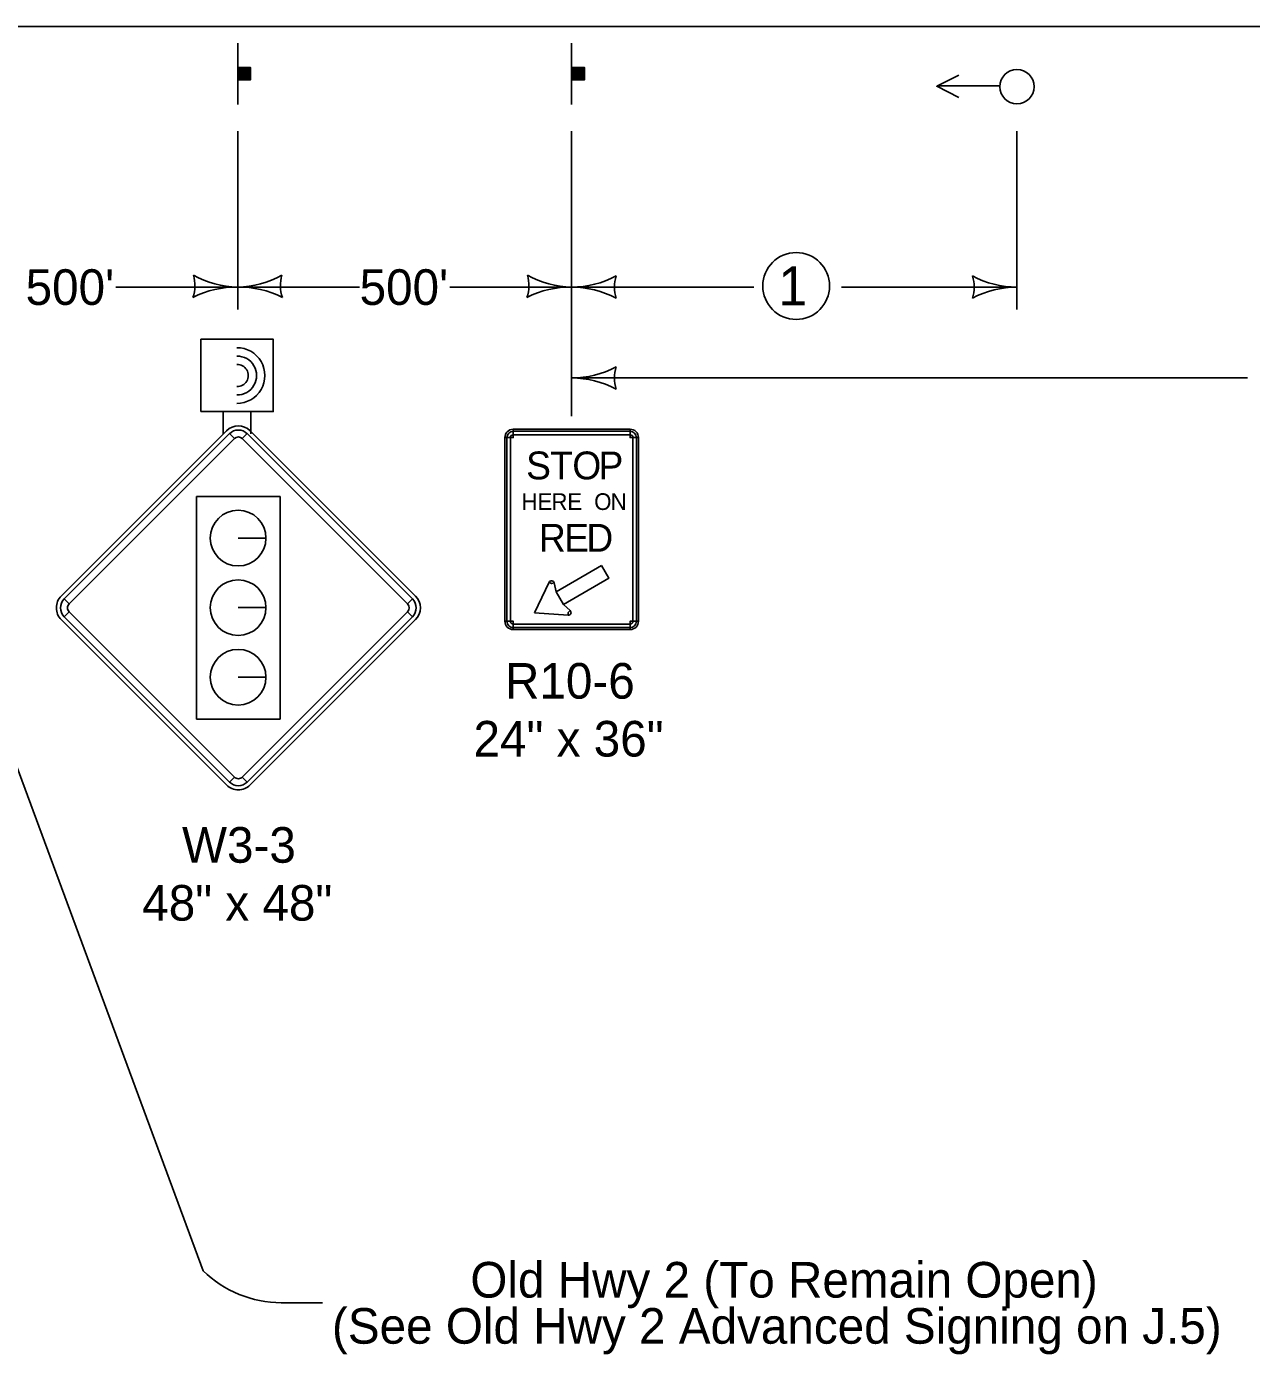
# Model space of a CAD drawing. Extents: x -2134934 to -2119606, y -2139046 to -2137036.
# Drawn here: x -2134479 to -2133929, y -2138264 to -2137668 of the extents above; entities that cross this region are included whole.
import ezdxf

# ---------------------------------------------------------------- set-up
doc = ezdxf.new("R2010")
doc.units = 0
for name, color, linetype in [('dsnCellElements', 7, 'Continuous'), ('dsnStdLabel', 7, 'Continuous'), ('dsnStdLineWork', 7, 'Continuous'), ('Level 2', 7, 'Continuous')]:
    doc.layers.add(name, color=color, linetype=linetype)

msp = doc.modelspace()

# ---------------------------------------------------------------- linework, layer by layer
at = {"layer": 'dsnCellElements'}
for centre, radius, start, end in [((-2134234.44, -2137783.48), 42.5, 270, 298.07249), ((-2134198.81, -2137825.98), 16.42, 162.26665, 197.73335), ((-2134234.44, -2137868.48), 42.5, 61.92751, 90)]:
    msp.add_arc(centre, radius, start, end, dxfattribs=at)
at = {"layer": 'dsnStdLabel'}
for p, q in [((-2134389.44, -2137849.65), (-2134463.68, -2137923.9)), ((-2134388.11, -2137850.98), (-2134385.9, -2137853.19)), ((-2134382.37, -2137853.19), (-2134380.16, -2137850.98)), ((-2134304.59, -2137923.9), (-2134378.83, -2137849.65)), ((-2134264.44, -2137852.75), (-2134260.69, -2137852.75)), ((-2134263.5, -2137852.75), (-2134261.94, -2137852.75)), ((-2134260.69, -2137852.75), (-2134260.69, -2137849)), ((-2134260.69, -2137851.5), (-2134260.69, -2137849.93)), ((-2134208.19, -2137849), (-2134208.19, -2137852.75)), ((-2134208.19, -2137849.93), (-2134208.19, -2137851.5)), ((-2134208.19, -2137852.75), (-2134204.44, -2137852.75)), ((-2134206.94, -2137852.75), (-2134205.38, -2137852.75)), ((-2134371.73, -2137897.87), (-2134384.23, -2137897.87)), ((-2134384.23, -2137897.87), (-2134371.73, -2137897.87)), ((-2134244.58, -2137917.73), (-2134243.48, -2137918.31)), ((-2134243.48, -2137918.31), (-2134242.26, -2137918.04)), ((-2134460.15, -2137927.43), (-2134462.36, -2137925.22)), ((-2134371.73, -2137929.12), (-2134384.23, -2137929.12)), ((-2134384.23, -2137929.12), (-2134371.73, -2137929.12)), ((-2134305.91, -2137925.22), (-2134308.12, -2137927.43)), ((-2134235.13, -2137930.38), (-2134235.98, -2137931.3)), ((-2134463.68, -2137934.5), (-2134389.44, -2138008.75)), ((-2134462.36, -2137933.18), (-2134460.15, -2137930.97)), ((-2134378.83, -2138008.75), (-2134304.59, -2137934.5)), ((-2134308.12, -2137930.97), (-2134305.91, -2137933.18)), ((-2134260.69, -2137935.24), (-2134264.44, -2137935.24)), ((-2134261.94, -2137935.24), (-2134263.5, -2137935.24)), ((-2134260.69, -2137938.99), (-2134260.69, -2137935.24)), ((-2134260.69, -2137938.06), (-2134260.69, -2137936.49)), ((-2134235.98, -2137931.3), (-2134236.03, -2137932.55)), ((-2134204.44, -2137935.24), (-2134208.19, -2137935.24)), ((-2134208.19, -2137935.24), (-2134208.19, -2137938.99)), ((-2134208.19, -2137936.49), (-2134208.19, -2137938.06)), ((-2134205.38, -2137935.24), (-2134206.94, -2137935.24)), ((-2134371.73, -2137960.37), (-2134384.23, -2137960.37)), ((-2134384.23, -2137960.37), (-2134371.73, -2137960.37)), ((-2134385.9, -2138005.21), (-2134388.11, -2138007.42)), ((-2134380.16, -2138007.42), (-2134382.37, -2138005.21))]:
    msp.add_line(p, q, dxfattribs=at)
for points in [[(-2134388.11, -2137850.98), (-2134462.36, -2137925.22), (-2134460.15, -2137927.43), (-2134385.9, -2137853.19), (-2134388.11, -2137850.98)], [(-2134305.91, -2137925.22), (-2134380.16, -2137850.98), (-2134382.37, -2137853.19), (-2134308.12, -2137927.43), (-2134305.91, -2137925.22)], [(-2134260.69, -2137938.99), (-2134208.19, -2137938.99), (-2134208.19, -2137935.24), (-2134204.44, -2137935.24), (-2134204.44, -2137852.75), (-2134208.19, -2137852.75), (-2134208.19, -2137849), (-2134260.69, -2137849), (-2134260.69, -2137852.75), (-2134264.44, -2137852.75), (-2134264.44, -2137935.24), (-2134260.69, -2137935.24), (-2134260.69, -2137938.99)], [(-2134261.94, -2137852.75), (-2134261.94, -2137935.24), (-2134263.5, -2137935.24), (-2134263.5, -2137852.75), (-2134261.94, -2137852.75)], [(-2134208.19, -2137851.5), (-2134260.69, -2137851.5), (-2134260.69, -2137849.93), (-2134208.19, -2137849.93), (-2134208.19, -2137851.5)], [(-2134206.94, -2137935.24), (-2134206.94, -2137852.75), (-2134205.38, -2137852.75), (-2134205.38, -2137935.24), (-2134206.94, -2137935.24)], [(-2134365.4, -2137879.26), (-2134402.87, -2137879.26), (-2134402.87, -2137979.15), (-2134365.4, -2137979.15), (-2134365.4, -2137879.26)], [(-2134221.07, -2137910.24), (-2134217.79, -2137915.93), (-2134238.1, -2137927.65), (-2134241.38, -2137921.97), (-2134221.07, -2137910.24)], [(-2134251.09, -2137931.37), (-2134236.03, -2137932.55), (-2134235.98, -2137931.3), (-2134235.13, -2137930.38), (-2134238.1, -2137927.65), (-2134241.38, -2137921.97), (-2134242.26, -2137918.04), (-2134243.48, -2137918.31), (-2134244.58, -2137917.73), (-2134251.09, -2137931.37)], [(-2134462.36, -2137933.18), (-2134388.11, -2138007.42), (-2134385.9, -2138005.21), (-2134460.15, -2137930.97), (-2134462.36, -2137933.18)], [(-2134380.16, -2138007.42), (-2134305.91, -2137933.18), (-2134308.12, -2137930.97), (-2134382.37, -2138005.21), (-2134380.16, -2138007.42)], [(-2134260.69, -2137936.49), (-2134208.19, -2137936.49), (-2134208.19, -2137938.06), (-2134260.69, -2137938.06), (-2134260.69, -2137936.49)]]:
    msp.add_lwpolyline(points, close=True, dxfattribs=at)
for centre in [(-2134384.23, -2137897.87), (-2134384.23, -2137929.12), (-2134384.23, -2137960.37)]:
    msp.add_circle(centre, 12.5, dxfattribs=at)
for centre, radius, start, end in [((-2134384.14, -2137854.96), 7.5, 44.99999, 134.99974), ((-2134384.14, -2137854.96), 5.62, 44.99999, 134.99974), ((-2134384.14, -2137854.96), 2.5, 44.99999, 134.99974), ((-2134260.69, -2137852.75), 3.75, 90.00021, 179.99985), ((-2134260.69, -2137852.75), 2.81, 90.00021, 179.99985), ((-2134260.69, -2137852.75), 1.25, 90.00021, 179.99985), ((-2134208.19, -2137852.75), 3.75, 0, 90.00021), ((-2134208.19, -2137852.75), 2.81, 0, 90.00021), ((-2134208.19, -2137852.75), 1.25, 0, 90.00021), ((-2134243.48, -2137918.31), 1.25, 12.62232, 152.27557), ((-2134458.38, -2137929.2), 7.5, 134.99974, 224.99995), ((-2134309.89, -2137929.2), 7.5, 315.00016, 44.9998), ((-2134458.38, -2137929.2), 5.62, 134.99974, 224.99995), ((-2134458.38, -2137929.2), 2.5, 134.99974, 224.99995), ((-2134309.89, -2137929.2), 2.5, 315.00016, 44.9998), ((-2134309.89, -2137929.2), 5.62, 315.00016, 44.9998), ((-2134235.98, -2137931.3), 1.25, 267.72427, 47.37758), ((-2134260.69, -2137935.24), 3.75, 179.99985, 270.00006), ((-2134260.69, -2137935.24), 2.81, 179.99985, 270.00006), ((-2134260.69, -2137935.24), 1.25, 179.99985, 270.00006), ((-2134208.19, -2137935.24), 3.75, 270.00006, 0.00027), ((-2134208.19, -2137935.24), 2.81, 270.00006, 0.00027), ((-2134208.19, -2137935.24), 1.25, 270.00006, 0.00027), ((-2134384.14, -2138003.45), 5.62, 224.99995, 315.00016), ((-2134384.14, -2138003.45), 2.5, 224.99995, 315.00016), ((-2134384.14, -2138003.45), 7.5, 224.99995, 315.00016)]:
    msp.add_arc(centre, radius, start, end, dxfattribs=at)
at = {"layer": 'dsnStdLineWork'}
msp.add_line((-2134884.44, -2137668.16), (-2133384.44, -2137668.16), dxfattribs=at)
msp.add_line((-2134884.44, -2137668.16), (-2133384.44, -2137668.16), dxfattribs=at)
at = {"layer": 'Level 2'}
for p, q in [((-2134384.44, -2137675.66), (-2134384.44, -2137703.16)), ((-2134234.44, -2137675.66), (-2134234.44, -2137703.16)), ((-2134384.03, -2137692.11), (-2134384.03, -2137686.52)), ((-2134383.75, -2137686.52), (-2134383.75, -2137692.11)), ((-2134383.48, -2137692.11), (-2134383.48, -2137686.52)), ((-2134383.22, -2137686.52), (-2134383.22, -2137692.11)), ((-2134383, -2137692.11), (-2134383, -2137686.52)), ((-2134382.79, -2137686.52), (-2134382.79, -2137692.11)), ((-2134382.45, -2137692.11), (-2134382.45, -2137686.52)), ((-2134382.19, -2137686.52), (-2134382.19, -2137692.11)), ((-2134381.97, -2137692.11), (-2134381.98, -2137686.52)), ((-2134381.65, -2137686.52), (-2134381.65, -2137692.11)), ((-2134381.27, -2137692.11), (-2134381.27, -2137686.52)), ((-2134380.84, -2137686.52), (-2134380.84, -2137692.11)), ((-2134380.62, -2137692.11), (-2134380.63, -2137686.52)), ((-2134380.2, -2137686.52), (-2134380.18, -2137692.11)), ((-2134379.98, -2137692.11), (-2134379.98, -2137686.52)), ((-2134379.66, -2137686.52), (-2134379.66, -2137692.11)), ((-2134379.43, -2137692.11), (-2134379.43, -2137686.52)), ((-2134379.12, -2137686.52), (-2134379.12, -2137692.11)), ((-2134234.03, -2137692.11), (-2134234.03, -2137686.52)), ((-2134233.75, -2137686.52), (-2134233.75, -2137692.11)), ((-2134233.49, -2137692.11), (-2134233.49, -2137686.52)), ((-2134233.22, -2137686.52), (-2134233.22, -2137692.11)), ((-2134233, -2137692.11), (-2134233, -2137686.52)), ((-2134232.79, -2137686.52), (-2134232.79, -2137692.11)), ((-2134232.45, -2137692.11), (-2134232.45, -2137686.52)), ((-2134232.19, -2137686.52), (-2134232.19, -2137692.11)), ((-2134231.97, -2137692.11), (-2134231.99, -2137686.52)), ((-2134231.65, -2137686.52), (-2134231.65, -2137692.11)), ((-2134231.27, -2137692.11), (-2134231.27, -2137686.52)), ((-2134230.84, -2137686.52), (-2134230.84, -2137692.11)), ((-2134230.62, -2137692.11), (-2134230.64, -2137686.52)), ((-2134230.2, -2137686.52), (-2134230.19, -2137692.11)), ((-2134229.98, -2137692.11), (-2134229.98, -2137686.52)), ((-2134229.66, -2137686.52), (-2134229.66, -2137692.11)), ((-2134229.44, -2137692.11), (-2134229.44, -2137686.52)), ((-2134229.12, -2137686.52), (-2134229.12, -2137692.11)), ((-2134042.18, -2137694.79), (-2134070.12, -2137694.79)), ((-2134399.95, -2138226.87), (-2134593.95, -2137702.64)), ((-2134384.44, -2137795.16), (-2134384.44, -2137715.16)), ((-2134234.44, -2137843.11), (-2134234.44, -2137715.16)), ((-2134034.44, -2137795.16), (-2134034.44, -2137715.16)), ((-2134439.19, -2137785.16), (-2134384.44, -2137785.16)), ((-2134384.44, -2137785.16), (-2134329.69, -2137785.16)), ((-2134289.19, -2137785.16), (-2134234.44, -2137785.16)), ((-2134234.44, -2137785.16), (-2134152.68, -2137785.16)), ((-2134113.22, -2137785.16), (-2134034.44, -2137785.16)), ((-2134234.44, -2137825.98), (-2133930.88, -2137825.98)), ((-2134390.98, -2137841.1), (-2134390.98, -2137851.1)), ((-2134378.48, -2137841.1), (-2134378.48, -2137851.1)), ((-2134364.86, -2138241.25), (-2134346.4, -2138241.25))]:
    msp.add_line(p, q, dxfattribs=at)
for points in [[(-2134384.35, -2137692.11), (-2134384.35, -2137686.48), (-2134378.72, -2137686.48), (-2134378.72, -2137692.11)], [(-2134234.35, -2137692.11), (-2134234.35, -2137686.48), (-2134228.72, -2137686.48), (-2134228.72, -2137692.11)], [(-2134400.98, -2137841.1), (-2134400.98, -2137808.6), (-2134368.48, -2137808.6), (-2134368.48, -2137841.1)]]:
    msp.add_lwpolyline(points, close=True, dxfattribs=at)
msp.add_lwpolyline([(-2134060.49, -2137689.98), (-2134070.49, -2137694.98), (-2134060.49, -2137699.98)], dxfattribs=at)
for centre, radius in [((-2134034.44, -2137695.16), 7.74), ((-2134133.59, -2137784.66), 15)]:
    msp.add_circle(centre, radius, dxfattribs=at)
for centre, radius, start, end in [((-2134420.06, -2137784.54), 16.42, 341.26665, 16.73335), ((-2134383.69, -2137742.67), 42.5, 240.92751, 268.9824), ((-2134385.2, -2137742.67), 42.5, 271.0176, 299.07249), ((-2134348.82, -2137784.54), 16.42, 163.26665, 198.73335), ((-2134270.06, -2137784.54), 16.42, 341.26665, 16.73335), ((-2134233.69, -2137742.67), 42.5, 240.92751, 268.9824), ((-2134234.44, -2137742.66), 42.5, 270, 298.07249), ((-2134198.81, -2137785.16), 16.42, 162.26665, 197.73335), ((-2134070.08, -2137785.16), 16.42, 342.26665, 17.73335), ((-2134034.44, -2137742.66), 42.5, 241.92751, 270), ((-2134385.17, -2137827.65), 42.5, 89.0176, 117.07249), ((-2134383.71, -2137827.65), 42.5, 62.92751, 90.9824), ((-2134235.17, -2137827.65), 42.5, 89.0176, 117.07249), ((-2134234.44, -2137827.66), 42.5, 61.92751, 90), ((-2134034.44, -2137827.66), 42.5, 90, 118.07249), ((-2134384.72, -2137824.87), 12.5, 269.40414, 90.54446), ((-2134384.72, -2137824.87), 12.5, 269.40414, 90.54446), ((-2134384.72, -2137824.87), 8.75, 269.40414, 90.54446), ((-2134384.72, -2137824.87), 5, 269.40414, 90.54446), ((-2134364.86, -2138191.25), 50, 225.43651, 270)]:
    msp.add_arc(centre, radius, start, end, dxfattribs=at)

# ---------------------------------------------------------------- texts
at = {"layer": 'dsnStdLabel'}
for s, height, p in [('S', 12.5, (-2134254.89, -2137871.5)), ('T', 12.5, (-2134244.13, -2137871.5)), ('O', 12.5, (-2134234.14, -2137871.5)), ('P', 12.5, (-2134222.39, -2137871.5)), ('H', 7.5, (-2134256.97, -2137885.25)), ('E', 7.5, (-2134249.82, -2137885.25)), ('R', 7.5, (-2134243.56, -2137885.25)), ('E', 7.5, (-2134236.41, -2137885.25)), ('O', 7.5, (-2134224.34, -2137885.25)), ('N', 7.5, (-2134216.96, -2137885.25)), ('R', 12.5, (-2134249.13, -2137904)), ('E', 12.5, (-2134237.8, -2137904)), ('D', 12.5, (-2134227.84, -2137904)), ('R10-6', 16, (-2134264.37, -2137969.99)), ('24" x 36"', 16, (-2134278.51, -2137995.99)), ('W3-3', 16, (-2134409.43, -2138043.67)), ('48" x 48"', 16, (-2134427.31, -2138069.67))]:
    msp.add_text(s, height=height, dxfattribs=at).set_placement(p)
at = {"layer": 'Level 2'}
for s, height, p in [("500'", 16, (-2134479.69, -2137793.16)), ("500'", 16, (-2134329.69, -2137793.16)), ('1', 17.5, (-2134141.65, -2137793.41)), ('Old Hwy 2 (To Remain Open)', 16, (-2134279.94, -2138238.95)), ('(See Old Hwy 2 Advanced Signing on J.5)', 16, (-2134342.09, -2138259.66))]:
    msp.add_text(s, height=height, dxfattribs=at).set_placement(p)

doc.saveas('drawing.dxf')
